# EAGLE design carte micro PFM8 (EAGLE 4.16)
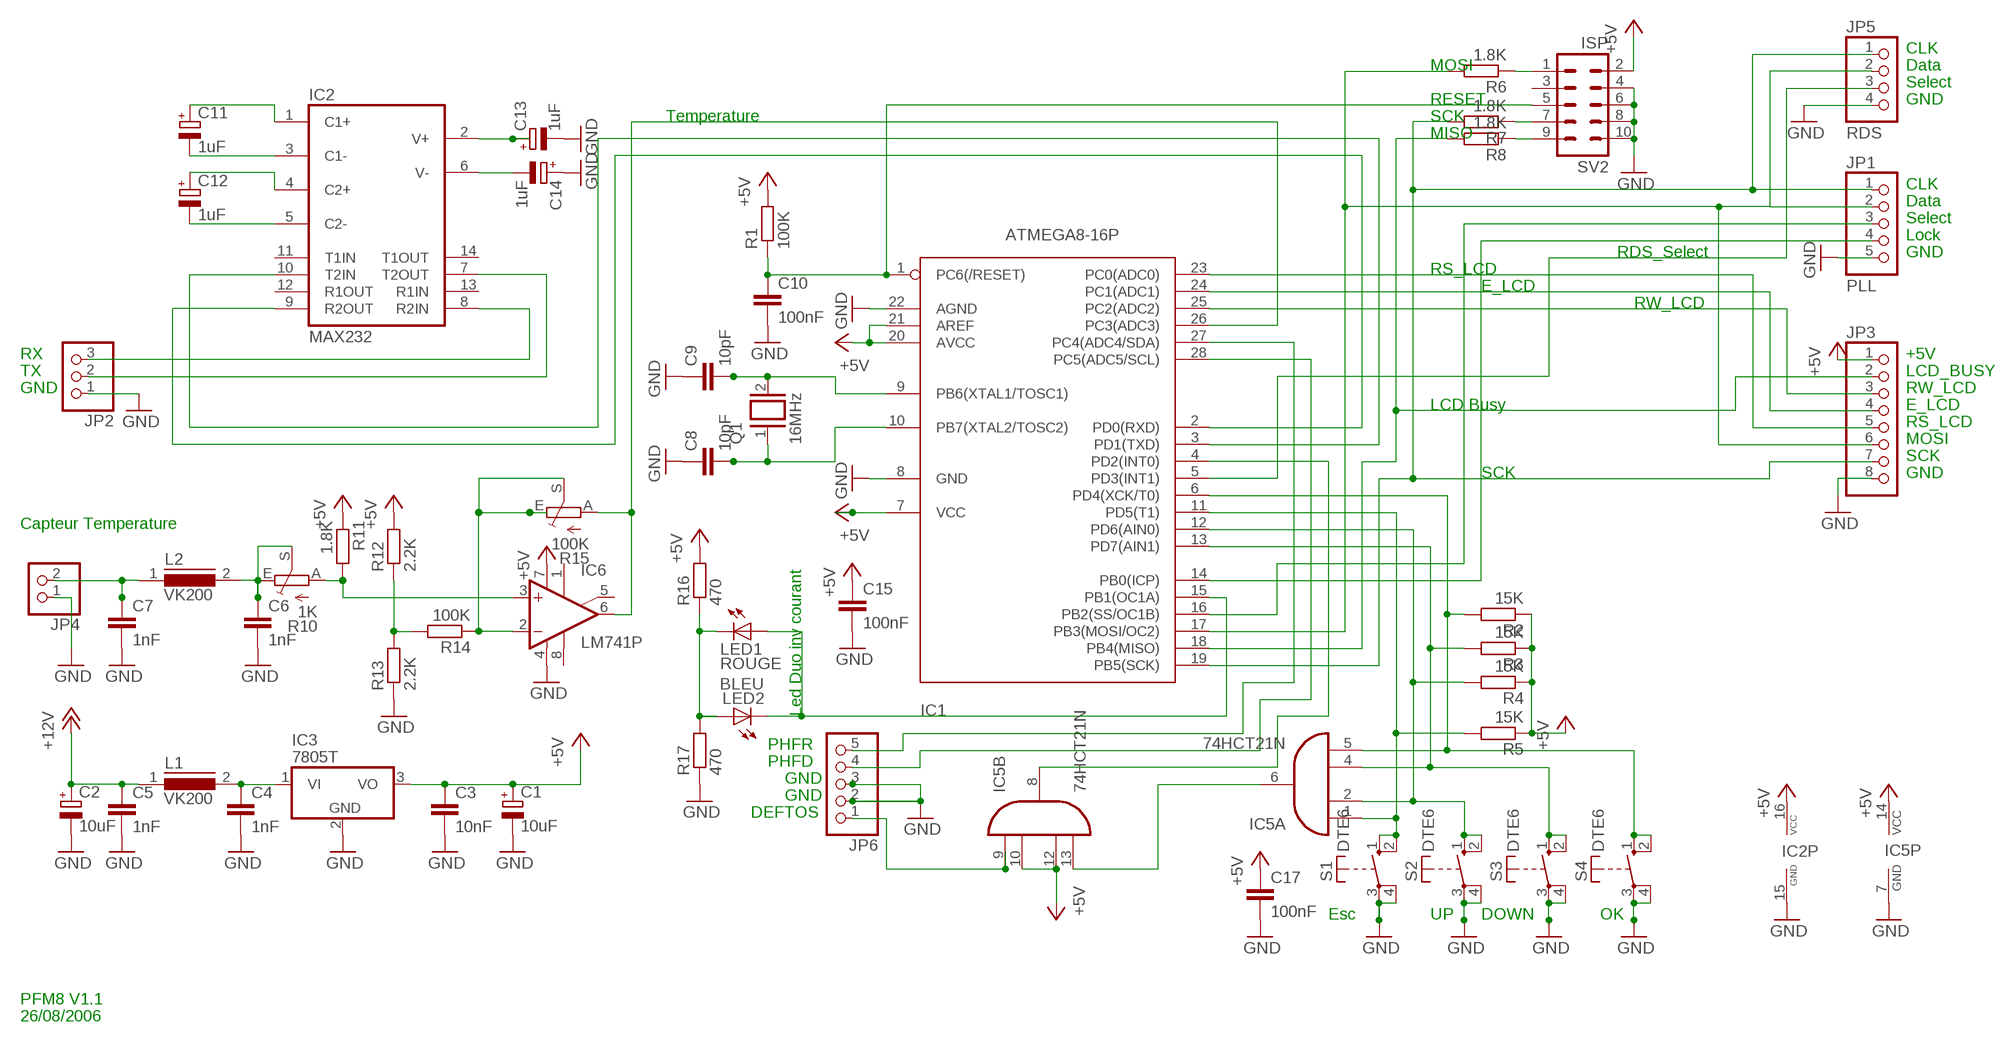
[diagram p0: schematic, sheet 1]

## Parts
C1  10uF  CPOL-EUE5-6  [E5-6]
C2  10uF  CPOL-EUE5-6  [E5-6]
C3  10nF  C-EU025-025X050  [C025-025X050]
C4  1nF  C-EU025-025X050  [C025-025X050]
C5  1nF  C-EU025-025X050  [C025-025X050]
C6  1nF  C-EU025-025X050  [C025-025X050]
C7  1nF  C-EU025-025X050  [C025-025X050]
C8  10pF  C-EU025-025X050  [C025-025X050]
C9  10pF  C-EU025-025X050  [C025-025X050]
C10  100nF  C-EU050-025X075  [C050-025X075]
C11  1uF  CPOL-EUE5-6  [E5-6]
C12  1uF  CPOL-EUE5-6  [E5-6]
C13  1uF  CPOL-EUE5-6  [E5-6]
C14  1uF  CPOL-EUE5-6  [E5-6]
C15  100nF  C-EU025-025X050  [C025-025X050]
C17  100nF  C-EU025-025X050  [C025-025X050]
IC1  ATMEGA8-16P  [DIL28-3]
IC2  MAX232  [DIL16]
IC3  7805T  [TO220H]
IC5  74HCT21N  [DIL14]
IC6  LM741P  [DIL08]
JP1  PLL  PINHD-1X5  [1X05]
JP2  PINHD-1X3  [1X03]
JP3  PINHD-1X8  [1X08]
JP4  PINHD-1X2  [1X02]
JP5  RDS  PINHD-1X4  [1X04]
JP6  PINHD-1X5  [1X05]
L1  VK200  B82131  [SUKW1-17]
L2  VK200  B82131  [SUKW1-17]
LED1  ROUGE  LED3MM  [LED3MM]
LED2  BLEU  LED3MM  [LED3MM]
Q1  16MHz  XTAL/S  [QS]
R1  100K  R-EU_0207/10  [0207/10]
R2  15K  R-EU_0207/10  [0207/10]
R3  15K  R-EU_0207/10  [0207/10]
R4  15K  R-EU_0207/10  [0207/10]
R5  15K  R-EU_0207/10  [0207/10]
R6  1.8K  R-EU_0207/10  [0207/10]
R7  1.8K  R-EU_0207/10  [0207/10]
R8  1.8K  R-EU_0207/10  [0207/10]
R10  1K  TRIM_EU-B25X  [B25X]
R11  1.8K  R-EU_0207/10  [0207/10]
R12  2.2K  R-EU_0207/10  [0207/10]
R13  2.2K  R-EU_0207/10  [0207/10]
R14  100K  R-EU_0207/10  [0207/10]
R15  100K  TRIM_EU-B25X  [B25X]
R16  470  R-EU_0207/10  [0207/10]
R17  470  R-EU_0207/10  [0207/10]
S1  DTE6  [DTE6]
S2  DTE6  [DTE6]
S3  DTE6  [DTE6]
S4  DTE6  [DTE6]
SV2  ISP  ML10  [ML10]

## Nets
+5V: C1.+ C3.1 C15.1 C17.1 IC1.7(VCC) IC1.20(AVCC) IC1.21(AREF) IC2.16(VCC) IC3.3(VO) IC5.10(B:I1) IC5.12(B:I2) IC5.14(P:VCC) IC6.7(V+) JP3.1 R1.2 R2.1 R3.1 R4.1 R5.1 R11.1 R12.2 R16.2 SV2.2
+12V: C2.+ C5.1 L1.1
GND: C1.- C2.- C3.2 C4.2 C5.2 C6.2 C7.2 C8.1 C9.1 C10.2 C13.- C14.+ C15.2 C17.2 IC1.8(GND) IC1.22(AGND) IC2.15(GND) IC3.2(GND) IC5.7(P:GND) IC6.4(V-) JP1.5 JP2.1 JP3.8 JP4.1 JP5.4 JP6.2 JP6.3 R13.1 R17.1 S1.3(P) S1.4(P) S2.3(P) S2.4(P) S3.3(P) S3.4(P) S4.3(P) S4.4(P) SV2.4 SV2.6 SV2.8 SV2.10
N$1: C7.1 JP4.2 L2.1
N$2: C4.1 IC3.1(VI) L1.2
N$3: C6.1 L2.2 R10.E R10.S
N$4: C9.2 IC1.9(PB6(XTAL1/TOSC1)) Q1.2
N$5: C10.1 IC1.1(PC6(/RESET)) R1.1 SV2.5
N$6: C8.2 IC1.10(PB7(XTAL2/TOSC2)) Q1.1
N$7: IC1.4(PD2(INT0)) IC5.8(B:O)
N$8: IC1.11(PD5(T1)) IC5.1(A:I0) R5.2 S1.1(S) S1.2(S)
N$9: IC1.12(PD6(AIN0)) IC5.2(A:I1) R4.2 S2.1(S) S2.2(S)
N$10: IC1.13(PD7(AIN1)) IC5.4(A:I2) R3.2 S3.1(S) S3.2(S)
N$11: IC1.16(PB2(SS/OC1B)) JP1.3
N$12: R6.1 SV2.1
N$13: IC1.5(PD3(INT1)) JP5.3
N$14: R8.1 SV2.9
N$15: IC1.14(PB0(ICP)) JP1.4
N$16: C13.+ IC2.2(V+)
N$21: R7.1 SV2.7
N$25: IC1.24(PC1(ADC1)) JP3.4
N$26: IC1.25(PC2(ADC2)) JP3.3
N$28: IC1.23(PC0(ADC0)) JP3.5
N$29: IC1.19(PB5(SCK)) JP1.1 JP3.7 JP5.1 R7.2
N$30: IC1.18(PB4(MISO)) JP3.2 R8.2
N$32: C14.- IC2.6(V-)
N$33: C11.+ IC2.1(C1+)
N$34: C11.- IC2.3(C1-)
N$35: C12.+ IC2.4(C2+)
N$36: C12.- IC2.5(C2-)
N$37: IC5.6(A:O) IC5.13(B:I3)
N$38: IC1.3(PD1(TXD)) IC2.10(T2IN)
N$39: IC1.2(PD0(RXD)) IC2.9(R2OUT)
N$40: IC2.8(R2IN) JP2.3
N$41: IC2.7(T2OUT) JP2.2
N$42: IC1.28(PC5(ADC5/SCL)) JP6.4
N$43: IC5.9(B:I0) JP6.1
N$44: IC1.27(PC4(ADC4/SDA)) JP6.5
N$45: IC6.3(+IN) R10.A R11.2
N$46: R12.1 R13.2 R14.2
N$47: IC6.2(-IN) R14.1 R15.E R15.S
N$48: IC1.26(PC3(ADC3)) IC6.6(OUT) R15.A
N$49: IC1.15(PB1(OC1A)) LED1.A LED2.K(C)
N$50: LED1.K(C) LED2.A R16.1 R17.2
N$52: IC1.17(PB3(MOSI/OC2)) JP1.2 JP3.6 JP5.2 R6.2
N$54: IC1.6(PD4(XCK/T0)) IC5.5(A:I3) R2.2 S4.1(S) S4.2(S)
Unconnected: IC2.11(T1IN) IC2.12(R1OUT) IC2.13(R1IN) IC2.14(T1OUT) IC6.1(ON1) IC6.5(ON2) IC6.8(OPT) SV2.3

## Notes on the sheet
- CLK
- MOSI | Data
- Select
- RESET | GND
- Temperature | SCK
- MISO
- CLK
- Data
- Select
- Lock
- RDS_Select | GND
- RS_LCD
- E_LCD
- RW_LCD
- RX | +5V
- TX | LCD_BUSY
- GND | RW_LCD
- LCD Busy | E_LCD
- RS_LCD
- MOSI
- SCK
- SCK | GND
- Capteur Temperature
- Led Duo inv courant
- PHFR
- PHFD
- GND
- GND
- DEFTOS
- Esc | UP | DOWN | OK
- PFM8 V1.1
- 26/08/2006

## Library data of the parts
C1 C2 C11-C14 = rcl:CPOL-EU: POLARIZED CAPACITOR, European symbol
C3-C10 C15 C17 = rcl:C-EU: CAPACITOR, European symbol
IC1 = avr:ATMEGA8*P: MICROCONTROLLER 8 Kbytes FLASH 1 kbytes SRAM 512 bytes EEPROM USART 4-channel 10 bit ADC 2-channel 8 bit ADC
IC2 = maxim:MAX232: RS232 TRANSEIVER
IC3 = linear:78*: Positive VOLTAGE REGULATOR Source: http://cache.national.com/ds/LM/LM78L05.pdf http://www.fairchildsemi.com/ds/LM/LM7805.pdf
IC5 = 74xx-eu:74*21: Dual 4-input AND gate
IC6 = linear:*741: OP AMP
JP1 JP6 = pinhead:PINHD-1X5: PIN HEADER
JP2 = pinhead:PINHD-1X3: PIN HEADER
JP3 = pinhead:PINHD-1X8: PIN HEADER
JP4 = pinhead:PINHD-1X2: PIN HEADER
JP5 = pinhead:PINHD-1X4: PIN HEADER
L1 L2 = inductors:B82131: INDUCTOR
LED1 LED2 = led:LED: LED
Q1 = special:XTAL/S: CRYSTAL
R1-R8 R11-R14 R16 R17 = rcl:R-EU_: RESISTOR, European symbol
R10 R15 = pot:TRIM_EU-: POTENTIOMETER
S1-S4 = switch-misc:DT: ITT SWITCH
SV2 = con-harting-ml:ML10: HARTING

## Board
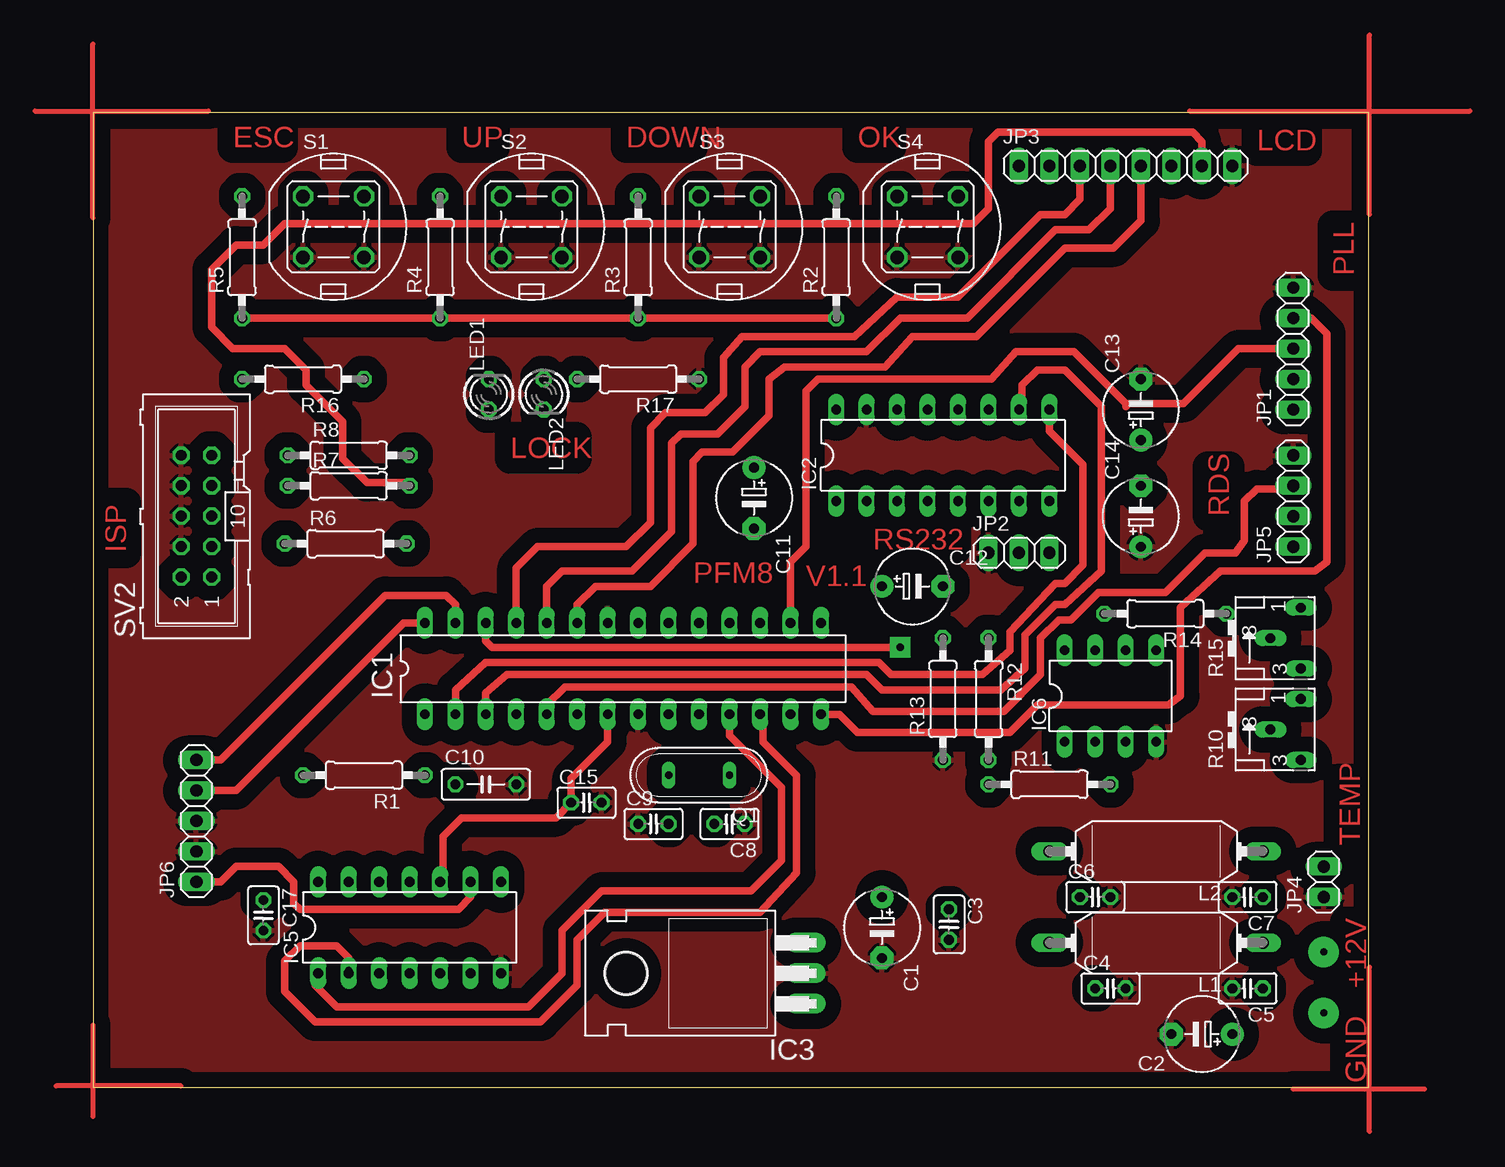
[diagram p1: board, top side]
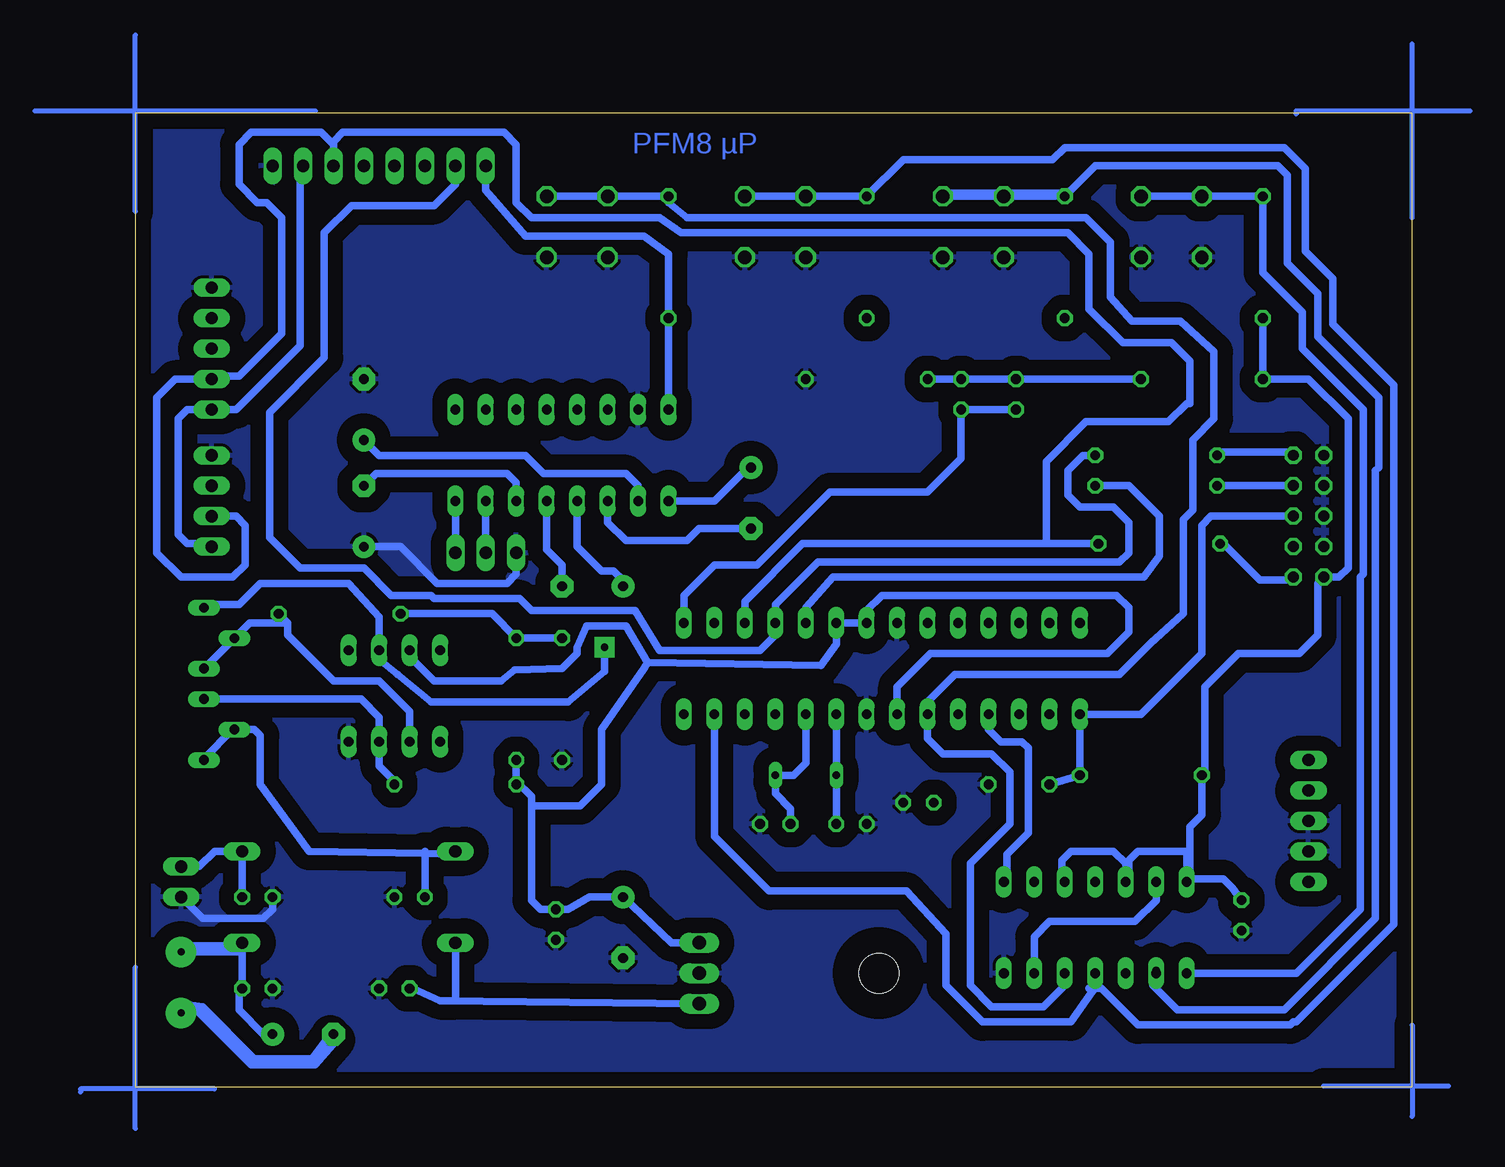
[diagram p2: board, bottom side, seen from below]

Size 106.35 x 81.27 mm. Coordinates in mm from the lower left corner, seen from the top.
Outline: 0,0 106.35,0 106.35,81.27 0,81.27 0,0
Copper layers (1*16): Top 0.035mm / dielectric 1.5mm / Bottom 0.035mm
Design rules "default": minimum track width 30mil, minimum drill 24mil, track to track 8mil, track to pad 8mil, pad to pad 8mil, via to via 8mil, smd to smd 8mil, copper to edge 40mil, drill to drill 8mil, minimum pad ring 10mil, minimum via ring 8mil, stop-mask expansion 4mil, vias tented up to drill 0mil, thermal gap 10mil

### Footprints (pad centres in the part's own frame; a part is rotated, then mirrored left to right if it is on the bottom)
E5-6 = drill 0.813 pad 1.905 round: + -2.54,0 | drill 0.813 pad 1.905 octagon: - 2.54,0
C025-025X050 = drill 0.813 octagon: 1 -1.27,0; 2 1.27,0
C050-025X075 = drill 0.813 octagon: 1 -2.54,0; 2 2.54,0
DIL28-3 = drill 0.813 long: 1 -16.51,-3.81; 2 -13.97,-3.81; 3 -11.43,-3.81; 4 -8.89,-3.81; 5 -6.35,-3.81; 6 -3.81,-3.81; 7 -1.27,-3.81; 8 1.27,-3.81; 9 3.81,-3.81; 10 6.35,-3.81; 11 8.89,-3.81; 12 11.43,-3.81; 13 13.97,-3.81; 14 16.51,-3.81; 15 16.51,3.81; 16 13.97,3.81; 17 11.43,3.81; 18 8.89,3.81; 19 6.35,3.81; 20 3.81,3.81; 21 1.27,3.81; 22 -1.27,3.81; 23 -3.81,3.81; 24 -6.35,3.81; 25 -8.89,3.81; 26 -11.43,3.81; 27 -13.97,3.81; 28 -16.51,3.81
DIL16 = drill 0.813 long: 1 -8.89,-3.81; 2 -6.35,-3.81; 3 -3.81,-3.81; 4 -1.27,-3.81; 5 1.27,-3.81; 6 3.81,-3.81; 7 6.35,-3.81; 8 8.89,-3.81; 9 8.89,3.81; 10 6.35,3.81; 11 3.81,3.81; 12 1.27,3.81; 13 -1.27,3.81; 14 -3.81,3.81; 15 -6.35,3.81; 16 -8.89,3.81
TO220H = drill 1.118 long: 1 -2.54,-10.16; 2 0,-10.16; 3 2.54,-10.16 | hole 3.302: 0,4.826
DIL14 = drill 0.813 long: 1 -7.62,-3.81; 2 -5.08,-3.81; 3 -2.54,-3.81; 4 0,-3.81; 5 2.54,-3.81; 6 5.08,-3.81; 7 7.62,-3.81; 8 7.62,3.81; 9 5.08,3.81; 10 2.54,3.81; 11 0,3.81; 12 -2.54,3.81; 13 -5.08,3.81; 14 -7.62,3.81
DIL08 = drill 0.813 long: 1 -3.81,-3.81; 2 -1.27,-3.81; 3 1.27,-3.81; 4 3.81,-3.81; 5 3.81,3.81; 6 1.27,3.81; 7 -1.27,3.81; 8 -3.81,3.81
1X05 = drill 1.016 long: 1 -5.08,0; 2 -2.54,0; 3 0,0; 4 2.54,0; 5 5.08,0
1X03 = drill 1.016 long: 1 -2.54,0; 2 0,0; 3 2.54,0
1X08 = drill 1.016 long: 1 -8.89,0; 2 -6.35,0; 3 -3.81,0; 4 -1.27,0; 5 1.27,0; 6 3.81,0; 7 6.35,0; 8 8.89,0
1X02 = drill 1.016 long: 1 -1.27,0; 2 1.27,0
1X04 = drill 1.016 long: 1 -3.81,0; 2 -1.27,0; 3 1.27,0; 4 3.81,0
SUKW1-17 = drill 1.016 long: 1 -8.89,0; 2 8.89,0
LED3MM = drill 0.813 octagon: A -1.27,0; K 1.27,0
QS = drill 0.61 long: 1 -2.54,0; 2 2.54,0
0207/10 = drill 0.813 octagon: 1 -5.08,0; 2 5.08,0
B25X = drill 0.813 long: A 2.54,-1.905; E -2.54,-1.905; S 0,0.635
DTE6 = drill 1.118 octagon: 1 -2.54,2.54; 2 2.54,2.54; 3 2.54,-2.54; 4 -2.54,-2.54
ML10 = drill 0.914 octagon: 1 -5.08,-1.27; 2 -5.08,1.27; 3 -2.54,-1.27; 4 -2.54,1.27; 5 0,-1.27; 6 0,1.27; 7 2.54,-1.27; 8 2.54,1.27; 9 5.08,-1.27; 10 5.08,1.27

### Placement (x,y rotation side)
C1  65.75,13.33 270 top
C2  92.42,4.44 180 top
C3  71.34,13.58 270 top
C4  84.8,8.25 0 top
C5  96.23,8.25 180 top
C6  83.53,15.87 0 top
C7  96.23,15.87 180 top
C8  53.05,21.97 180 top
C9  46.7,21.97 0 top
C10  32.73,25.27 0 top
C11  55.08,49.14 270 top
C12  68.29,41.78 0 top
C13  87.34,56.51 90 top
C14  87.34,47.62 90 top
C15  41.11,23.74 0 top
C17  14.19,14.35 270 top
IC1  44.16,34.92 0 top
IC2  70.83,52.7 0 top
IC3  49.24,9.52 90 top
IC5  26.38,13.33 0 top
IC6  84.8,32.63 0 top
JP1  100.04,61.59 90 top
JP2  77.18,44.57 0 top
JP3  86.07,76.83 0 top
JP4  102.58,17.14 90 top
JP5  100.04,48.89 90 top
JP6  8.6,22.22 90 top
L1  88.61,12.06 180 top
L2  88.61,19.68 180 top
LED1  32.98,57.78 90 top
LED2  37.55,57.78 270 top
Q1  50.51,26.03 180 top
R1  22.57,26.03 180 top
R2  61.94,69.21 90 top
R3  45.43,69.21 90 top
R4  28.92,69.21 90 top
R5  12.41,69.21 90 top
R6  21.04,45.33 0 top
R7  21.3,50.16 0 top
R8  21.3,52.7 0 top
R10  98.77,29.84 90 top
R11  79.72,25.27 0 top
R12  74.64,32.38 270 top
R13  70.83,32.38 90 top
R14  89.37,39.49 180 top
R15  98.77,37.46 90 top
R16  17.49,59.05 180 top
R17  45.43,59.05 180 top
S1  20.03,71.75 0 top
S2  36.54,71.75 0 top
S3  53.05,71.75 0 top
S4  69.56,71.75 0 top
SV2  8.6,47.62 90 top

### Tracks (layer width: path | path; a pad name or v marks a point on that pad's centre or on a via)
+5V
  Top 0.61: R5.1 R4.1 R3.1 | R3.1 45.68,64.13 | R3.1 R2.1 | IC1.7 42.89,28.82 39.84,25.78 C15.1 38.57,22.47 35.78,22.47 | 35.78,22.47 30.7,22.47 29.17,20.95 29.17,17.14 28.92,16.89 IC5.10 | 35.78,22.47 36.03,22.47
  Bottom 0.61: IC3.3 61.68,12.06 C1.+ 68.54,15.87 70.32,14.85 C3.1 72.61,14.85 73.37,15.62 73.37,23.49 | 73.37,23.49 73.37,24.25 74.64,25.52 | IC6.7 83.53,35.94 81.5,33.9 75.91,33.9 74.77,34.79 70.83,34.92 69.56,36.19 69.56,36.7 68.8,38.48 65.49,38.48 63.72,35.43 | 73.37,23.49 69.3,23.49 67.53,25.27 67.53,29.84 63.97,34.92 63.72,35.43 | IC2.16 R2.1 61.94,69.46 63.97,70.99 73.88,70.99 77.18,74.8 JP3.1 | 12.41,64.38 R5.1 R16.2 8.6,59.05 5.3,55.75 5.3,43.3 6.06,42.54 SV2.2 7.84,42.03 7.84,37.71 9.36,36.19 14.44,36.19 17.23,33.4 17.23,26.03 R1.2 17.49,22.73 18.5,21.71 18.5,17.39 IC5.14 | C17.1 14.95,16.63 15.71,17.39 18.25,17.39 18.5,17.14 IC5.14 | IC1.21 45.17,38.73 | IC1.21 IC1.20 47.97,36.95 49.24,35.17 63.72,35.43 | IC5.14 18.76,19.68 22.82,19.68 23.58,18.92 23.58,17.14 23.84,16.89 IC5.12 23.84,18.66 24.85,19.68 28.41,19.68 29.17,18.92 29.17,17.39 IC5.10 | 74.64,25.52 R11.1 | 74.64,25.52 R12.2 | IC1.7 42.89,33.4 40.09,36.19 25.36,36.19 23.58,37.97 23.58,40 24.6,41.02 44.16,41.02 45.43,39.75 IC1.21
+12V
  Bottom 0.61: C2.+ 95.72,4.44 97.75,6.47 97.75,8 C5.1 97.5,11.3 | L1.1 97.75,12.06 97.5,11.81 | 97.5,11.3 102.07,11.3 | 97.5,11.3 97.5,11.81 | 97.5,11.81 102.07,11.81
GND
  Bottom 0.61: JP2.1 74.64,42.79 75.4,42.03 81.24,42.03 84.29,45.08 C14.+ | C7.2 94.96,14.85 95.72,14.09 100.8,14.09 JP4.1
  pour Top (isolate 1.27): -0.04,81.4 106.13,81.4 106.13,0.12 -0.04,0.12
  pour Bottom (isolate 1.27): -0.04,81.4 106.39,81.4 106.39,0.12 -0.04,0.12
N$1
  Bottom 0.61: JP4.2 101.05,18.41 99.78,19.68 L2.1 | L2.1 97.5,19.93 | C7.1 L2.1
N$2
  Bottom 0.61: IC3.1 80.99,7.23 | C4.1 83.27,8.25 80.99,7.23 | 80.99,7.23 79.72,7.23 L1.2
N$3
  Bottom 0.61: R10.E 100.67,27.43 98.26,29.84 R10.S 96.48,29.84 95.97,29.33 95.97,25.27 91.91,19.68 82.26,19.51 | L2.2 79.97,19.43 82.26,19.51 | 82.26,19.51 82.26,19.68 C6.1
N$4
  Bottom 0.61: C9.2 Q1.2 IC1.9
N$5
  Top 0.61: 27.39,26.28 R1.1
  Bottom 0.61: C10.1 R1.1 27.65,30.86 27.39,31.11 IC1.1 22.57,31.11 17.49,36.19 17.49,46.86 16.73,47.62 SV2.5
N$6
  Bottom 0.61: 51.78,21.71 C8.2 51.78,23.24 53.05,24.51 53.05,25.52 52.79,25.78 Q1.1 | Q1.1 52.79,26.03 | IC1.10 50.51,27.05 51.52,26.03 Q1.1
N$7
  Bottom 0.61: IC1.4 35.27,29.84 34.25,28.82 32.47,28.82 31.97,28.32 31.97,21.2 33.74,19.43 33.74,17.39 IC5.8 34.25,16.89
N$8
  Top 0.61: 18.76,9.27 IC5.1 18.5,9.77 18.5,8.5 20.28,6.73 36.28,6.73 39.08,9.52 39.08,13.08 42.38,16.38 54.83,16.38 57.37,18.92 57.37,25.01 53.05,29.33 IC1.11
  Bottom 0.61: R5.2 12.15,74.29 | R5.2 S1.1 S1.2 R5.2 | R5.2 12.41,67.94 9.11,64.64 9.11,61.59 4.03,56.51 4.03,42.79 4.28,42.54 4.28,14.85 9.61,9.52 IC5.1
N$9  (via drill 0.6)
  Top 0.61: v21.3,9.77 21.3,10.79 20.28,11.81 17.23,11.81 15.96,10.54 15.96,8 18.5,5.46 37.3,5.46 40.35,8.5 40.35,12.31 42.63,14.6 55.59,14.6 58.64,17.9 58.64,26.03 55.84,28.82 55.84,30.6 55.59,30.86 IC1.12
  Bottom 0.61: 28.66,74.29 R4.2 S2.1 S2.2 38.82,74.54 28.66,74.54 26.38,76.83 11.14,76.83 10.38,76.07 10.38,68.7 7.84,66.16 7.84,62.61 2.76,57.53 2.76,51.68 3.01,51.43 3.01,14.09 10.63,6.47 19.52,6.47 21.55,8.5 21.55,9.01 21.3,9.27 IC5.2 v21.3,9.77
N$10
  Bottom 0.61: R3.2 S3.1 S3.2 R3.2 | 26.63,8 26.38,8.25 IC5.4 | 26.63,8 28.41,5.46 35.78,5.46 38.82,8.5 38.82,12.82 42.13,16.38 53.56,16.38 58.13,20.95 IC1.13 58.13,31.36 | R3.2 42.38,77.34 29.93,77.34 28.92,78.35 10.63,78.35 8.85,76.58 8.85,69.72 6.57,67.43 6.57,63.62 1.49,58.54 1.49,13.58 9.61,5.46 9.87,5.46 10.12,5.2 22.82,5.2 25.87,8.25 26.89,8.25 26.63,8
N$11
  Top 0.61: JP1.3 95.47,61.59 90.89,57.02 86.32,57.02 86.07,56.76 86.07,57.02 81.75,61.34 76.92,61.34 74.89,59.05 60.41,59.05 59.4,58.03 59.4,45.08 58.13,43.81 58.13,39.49 58.38,39.24 58.38,38.98 IC1.16
N$12
  Bottom 0.61: SV2.1 10.12,42.29 12.66,42.29 15.71,45.33 R6.1
N$13
  Top 0.61: IC1.5 37.81,31.87 39.33,33.4 63.21,33.4 64.99,31.36 75.91,31.36 78.96,34.41 78.96,37.46 80.48,38.98 81.5,38.98 83.78,41.27 89.37,41.27 92.67,44.57 95.21,44.57 95.97,45.59 95.97,48.89 96.99,49.91 99.53,49.91 100.04,50.41 JP5.3
N$14
  Bottom 0.61: R8.1 16.47,52.95 10.12,52.95 SV2.9
N$15
  Top 0.61: IC1.14 60.41,31.36 | 60.92,30.86 IC1.14 | JP1.4 101.56,64.13 102.83,62.86 102.83,43.81 101.82,43.05 93.94,43.05 90.64,40 90.64,32.63 89.62,31.87 78.7,31.87 76.42,29.59 63.72,29.59 62.19,31.11 IC1.14
N$16
  Bottom 0.61: C13.+ 86.07,52.7 75.4,52.7 | 75.4,52.7 74.89,52.7 | 64.48,48.64 IC2.2 64.48,50.16 65.49,51.18 72.35,51.18 73.88,52.7 75.4,52.7
N$17  (via drill 0.6 pad 2.54)
  other vias: 102.58,11.3
N$18  (via drill 0.6 pad 2.54)
  other vias: 102.58,6.22
N$19
  Bottom 0.61: 89.62,3.93 91.4,1.9 96.74,1.9 101.31,6.47 101.82,6.47 | 101.82,6.47 102.07,6.47 102.07,6.22 101.82,6.47
N$20
  Bottom 0.61: 90.13,4.44 91.66,2.41 96.48,2.41 100.8,6.73 102.58,6.98
N$21
  Bottom 0.61: SV2.7 R7.1
N$22
  Bottom 0.406: -0.04,72.51 -0.04,86.99
N$23
  Bottom 0.406: -4.86,81.4 9.61,81.4 9.61,81.15
N$24
  Bottom 0.406: 91.4,81.4 114.77,81.4
N$25
  Top 0.61: JP3.4 84.8,73.27 83.02,71.5 80.23,71.5 72.86,64.13 67.27,64.13 64.48,61.34 55.59,61.34 54.32,60.07 54.32,56.76 52.03,54.48 48.98,54.48 48.22,53.72 48.22,46.35 44.92,43.05 39.08,43.05 37.81,41.78 IC1.24
N$26
  Top 0.61: JP3.3 82.26,74.04 80.99,72.77 78.96,72.77 72.1,65.91 67.02,65.91 63.46,62.61 54.06,62.61 52.54,60.83 52.54,57.78 51.02,56.26 47.71,56.26 46.44,54.99 46.44,47.11 44.41,45.08 37.05,45.08 35.27,43.3 IC1.25
N$27
  Bottom 0.406: 106.39,73.02 106.39,87.75
N$28
  Top 0.61: JP3.5 87.34,72.26 85.05,69.97 80.99,69.97 73.62,62.61 68.29,62.61 66,60.07 57.62,60.07 56.35,59.05 56.35,56 53.3,52.95 50.76,52.95 50,52.19 50,45.33 46.44,41.78 41.87,41.78 40.35,40.25 40.35,39.24 40.09,38.98 IC1.23
N$29
  Top 0.61: JP3.7 92.42,78.86 91.66,79.62 75.4,79.62 74.64,78.86 74.64,73.27 73.37,72 15.96,72 14.19,70.23 11.9,70.23 9.87,68.19 9.87,63.37 11.65,61.59 15.96,61.59 17.74,59.81 17.74,58.54 20.79,55.49 20.79,52.45 22.82,50.41 26.12,50.41 R7.2 26.12,50.16
  Bottom 0.61: JP3.7 92.67,76.58 92.67,61.84 98.01,56.51 JP1.1 102.07,56.51 102.83,55.75 102.83,46.1 102.07,45.33 100.29,45.33 JP5.1 | R7.2 23.58,50.16 21.04,47.62 21.04,44.32 22.31,42.54 48.22,42.54 50.51,40 IC1.19
N$30
  Bottom 0.61: R8.2 27.39,52.7 28.66,51.43 28.66,49.4 27.65,48.38 24.85,48.38 23.58,47.11 23.58,44.57 24.35,43.81 49.49,43.81 53.05,40.25 IC1.18 53.05,37.71 54.32,36.44 62.7,36.44 64.73,39.75 73.37,39.75 74.38,40.76 81.5,40.76 81.75,41.02 85.05,41.02 87.34,43.3 92.67,43.3 95.21,45.84 95.21,56.26 90.64,60.83 90.64,71.24 88.35,73.53 81.5,73.53 79.72,75.31 JP3.2
N$31
  Bottom 0.406: 106.39,-3.43 106.39,10.03
N$32
  Bottom 0.61: C14.- 86.32,51.18 75.4,51.18 74.64,50.41 IC2.6
N$33
  Bottom 0.61: C11.+ 55.33,51.68 58.13,48.89 IC2.1
N$34
  Bottom 0.61: C11.- 59.4,46.6 60.41,45.59 65.49,45.59 67.02,47.11 IC2.3
N$35
  Bottom 0.61: IC2.4 69.56,45.08 67.53,43.05 66.51,43.05 65.75,42.29 C12.+
N$36
  Bottom 0.61: IC2.5 72.1,44.83 70.83,43.56 C12.-
N$37
  Bottom 0.61: IC5.6 31.46,12.57 30.19,13.84 23.08,13.84 21.3,15.62 IC5.13
N$38
  Top 0.61: IC1.3 32.73,32.89 34.51,34.41 64.48,34.41 65.75,33.14 75.65,33.14 77.69,34.92 77.69,37.71 80.23,40.25 80.99,40.25 84.04,43.05 84.04,56.76 80.99,59.81 78.7,59.81 77.43,58.54 77.43,56.76 IC2.10
N$39
  Top 0.61: IC2.9 79.72,54.73 82.51,51.94 82.51,43.56 80.99,42.03 80.23,42.03 76.42,37.97 76.42,36.44 74.13,34.41 66.51,34.41 65.49,35.43 32.73,35.43 30.19,33.14 30.19,31.36 29.93,31.11 IC1.2
N$40
  Bottom 0.61: JP2.3 IC2.8
N$41
  Bottom 0.61: JP2.2 IC2.7
N$42
  Top 0.61: JP6.4 11.9,24.76 25.87,38.73 IC1.28
N$43
  Top 0.61: JP6.1 10.63,17.14 11.9,18.41 15.46,18.41 16.73,17.14 16.73,15.36 17.23,14.85 30.44,14.85 31.46,15.87 IC5.9
N$44
  Top 0.61: IC1.27 29.93,38.73 30.19,38.98 30.19,40.25 29.43,41.02 24.35,41.02 10.63,27.3 JP6.5
N$45
  Bottom 0.61: IC6.3 86.07,30.09 | R11.2 84.8,25.52 86.07,26.79 IC6.3 | R10.A 87.59,32.38 86.07,30.86 IC6.3
N$46
  Bottom 0.61: R13.2 R12.1 76.67,39.49 R14.2
N$47
  Bottom 0.61: IC6.2 83.53,31.36 86.07,33.9 89.88,33.9 93.69,37.71 93.69,38.73 | 93.69,38.73 R14.1 | R15.S R15.E | R15.S 98.01,37.46 | R15.S 96.86,38.73 93.69,38.73
N$48  (via drill 0.6 pad 1.68)
  Top 0.61: IC1.26 32.73,37.21 33.24,36.7 v67.27,36.7
  Bottom 0.61: R15.A 100.42,40.25 97.75,40.25 95.97,42.03 88.61,42.03 86.07,39.24 IC6.6 86.07,35.68 84.54,34.41 81.75,32.13 70.32,32.13 67.27,34.67 v67.27,36.7
N$49
  Bottom 0.406: LED2.K 37.55,56.76 37.3,56.51
  Bottom 0.61: IC1.15 60.67,41.02 58.13,43.56 54.57,43.56 48.48,49.65 40.35,49.65 37.55,52.45 LED2.K | 37.3,56.51 LED1.A
N$50
  Bottom 0.61: R16.1 LED1.K 37.05,59.05 37.3,59.3 LED2.A R17.2
N$52
  Bottom 0.61: 25.87,45.33 R6.2 30.44,45.33 | 30.44,45.33 50.76,45.33 55.59,40.51 IC1.17 | 30.44,45.33 30.44,52.19 27.14,55.49 20.28,55.49 18.76,57.02 18.5,57.02 18.5,60.57 20.03,62.1 24.09,62.1 26.89,64.89 26.89,69.46 28.66,71.24 60.92,71.24 62.7,72.51 73.37,72.51 74.64,73.78 74.64,78.61 75.65,79.62 89.12,79.62 89.88,78.86 JP3.6 89.88,78.61 90.89,79.62 96.74,79.62 97.75,78.61 97.75,75.31 96.23,73.78 95.47,73.78 94.2,72.51 94.2,62.86 97.75,59.3 100.04,59.3 100.29,59.05 JP1.2 103.09,59.05 104.61,57.53 104.61,44.57 102.58,42.54 98.26,42.54 97.24,43.56 97.24,46.86 98.01,47.62 JP5.2
N$53
  Bottom 0.406: 99.78,-0.13 110.96,-0.13 110.96,-0.39
N$54
  Bottom 0.61: S4.1 66.76,74.29 | S4.1 S4.2 | S4.1 R2.2 61.94,73.78 60.41,72.51 27.14,72.51 25.11,70.48 25.11,65.91 23.33,63.88 19.27,63.88 16.47,61.34 16.47,55.75 18.25,53.97 18.25,48.13 19.01,47.37 19.01,39.49 21.81,36.95 | 21.81,36.95 24.35,34.41 38.06,34.41 40.35,32.13 IC1.6 40.35,29.08 39.08,27.81 35.01,27.81 33.49,26.28 33.49,21.97 36.79,18.66 36.79,8.5 35.01,6.73 30.7,6.73 28.92,8.5 IC5.5 | 21.81,36.95 21.55,37.21
N$55
  Bottom 0.406: 7.33,0.12 -3.09,0.12
N$56
  Bottom 0.406: -0.04,5.2 -0.04,-2.42
N$57
  Top 0.406: -0.04,5.2 -0.04,-2.42
N$58
  Top 0.406: 7.33,0.12 -3.09,0.12
N$59
  Top 0.406: 100.04,-0.13 110.96,-0.13
N$60
  Top 0.406: 106.39,-3.69 106.39,10.03
N$61
  Top 0.406: 106.39,72.77 106.39,87.75
N$62
  Top 0.406: 91.4,81.4 114.77,81.4
N$63
  Top 0.406: -4.86,81.4 9.61,81.4
N$64
  Top 0.406: -0.04,72.51 -0.04,86.99

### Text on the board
Top: ESC | UP | DOWN | OK | LCD | PLL | LOCK | RDS | ISP | RS232 | PFM8 | V1.1 | TEMP | +12V | GND
Bottom: PFM8 µP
